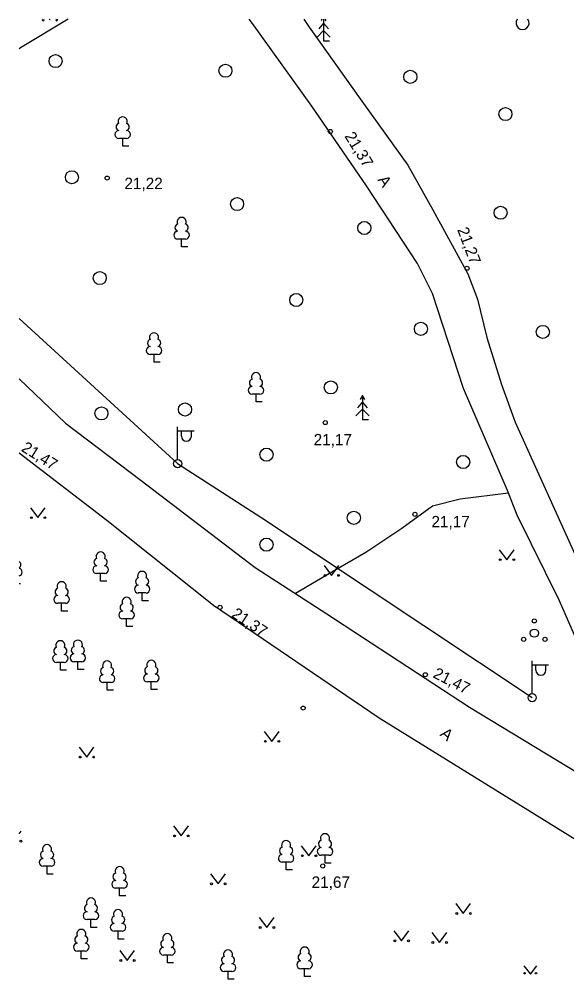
# Model space of a CAD drawing. Extents: x 714391 to 714584, y 6589993 to 6590151.
# Drawn here: x 714390.6 to 714424.1, y 6590092.2 to 6590151.1 of the extents above; entities that cross this region are included whole.
import ezdxf

# ---------------------------------------------------------------- set-up
doc = ezdxf.new("R2010")
doc.units = 0
for name, color, linetype in [('HALJASTUS', 7, 'Continuous'), ('KORGUS', 7, 'Continuous'), ('MPKAABEL', 7, 'Continuous'), ('POST', 7, 'Continuous'), ('PUU', 7, 'Continuous'), ('TEE', 7, 'Continuous')]:
    doc.layers.add(name, color=color, linetype=linetype)

msp = doc.modelspace()

# ---------------------------------------------------------------- linework, layer by layer
at = {"layer": 'HALJASTUS'}
for p, q in [((714392.483, 6590151.075), (714392.51, 6590151.04)), ((714392.51, 6590151.04), (714392.536, 6590151.075)), ((714391.327, 6590121.227), (714391.79, 6590120.62)), ((714391.79, 6590120.62), (714392.236, 6590121.227)), ((714419.987, 6590118.657), (714420.45, 6590118.05)), ((714420.45, 6590118.05), (714420.896, 6590118.657)), ((714409.277, 6590117.697), (714409.74, 6590117.09)), ((714409.74, 6590117.09), (714410.186, 6590117.697)), ((714405.627, 6590107.557), (714406.09, 6590106.95)), ((714406.09, 6590106.95), (714406.536, 6590107.557)), ((714394.307, 6590106.597), (714394.77, 6590105.99)), ((714394.77, 6590105.99), (714395.216, 6590106.597)), ((714400.077, 6590101.777), (714400.54, 6590101.17)), ((714400.54, 6590101.17), (714400.986, 6590101.777)), ((714390.649, 6590101.299), (714390.766, 6590101.457)), ((714407.887, 6590100.567), (714408.35, 6590099.96)), ((714408.35, 6590099.96), (714408.796, 6590100.567)), ((714402.337, 6590098.847), (714402.8, 6590098.24)), ((714402.8, 6590098.24), (714403.246, 6590098.847)), ((714417.327, 6590097.037), (714417.79, 6590096.43)), ((714417.79, 6590096.43), (714418.236, 6590097.037)), ((714405.317, 6590096.177), (714405.78, 6590095.57)), ((714405.78, 6590095.57), (714406.226, 6590096.177)), ((714413.547, 6590095.367), (714414.01, 6590094.76)), ((714414.01, 6590094.76), (714414.456, 6590095.367)), ((714415.867, 6590095.267), (714416.33, 6590094.66)), ((714416.33, 6590094.66), (714416.776, 6590095.267)), ((714396.787, 6590094.167), (714397.25, 6590093.56)), ((714397.25, 6590093.56), (714397.696, 6590094.167)), ((714421.484, 6590093.227), (714421.889, 6590092.722)), ((714421.889, 6590092.722), (714422.284, 6590093.227))]:
    msp.add_line(p, q, dxfattribs=at)
for points in [[(714393.647, 6590151.075), (714390.73, 6590149.32), (714390.649, 6590149.275)], [(714420.55, 6590122.12), (714417.59, 6590121.75), (714415.91, 6590121.32), (714414.04, 6590119.96), (714411.84, 6590118.48), (714409.76, 6590117.28), (714407.53, 6590115.99)]]:
    msp.add_lwpolyline(points, dxfattribs=at)
for centre, radius in [((714392.87, 6590148.52), 0.4), ((714403.25, 6590147.93), 0.4), ((714414.55, 6590147.56), 0.4), ((714420.36, 6590145.28), 0.4), ((714393.87, 6590141.42), 0.4), ((714403.96, 6590139.78), 0.4), ((714420.07, 6590139.25), 0.4), ((714411.74, 6590138.32), 0.4), ((714395.57, 6590135.26), 0.4), ((714407.58, 6590133.92), 0.4), ((714415.2, 6590132.16), 0.4), ((714422.65, 6590131.97), 0.4), ((714409.69, 6590128.58), 0.4), ((714400.78, 6590127.23), 0.4), ((714395.67, 6590126.99), 0.4), ((714405.76, 6590124.47), 0.4), ((714417.78, 6590124.02), 0.4), ((714411.1, 6590120.61), 0.4), ((714391.389, 6590120.62), 0.055), ((714392.218, 6590120.62), 0.055), ((714405.76, 6590118.97), 0.4), ((714420.049, 6590118.05), 0.055), ((714420.878, 6590118.05), 0.055), ((714409.339, 6590117.09), 0.055), ((714410.168, 6590117.09), 0.055), ((714422.13, 6590114.31), 0.125), ((714422.13, 6590113.56), 0.25), ((714421.48, 6590113.185), 0.125), ((714422.78, 6590113.185), 0.125), ((714405.689, 6590106.95), 0.055), ((714406.518, 6590106.95), 0.055), ((714394.369, 6590105.99), 0.055), ((714395.198, 6590105.99), 0.055), ((714400.139, 6590101.17), 0.055), ((714400.968, 6590101.17), 0.055), ((714390.748, 6590100.85), 0.055), ((714407.949, 6590099.96), 0.055), ((714408.778, 6590099.96), 0.055), ((714402.399, 6590098.24), 0.055), ((714403.228, 6590098.24), 0.055), ((714417.389, 6590096.43), 0.055), ((714418.218, 6590096.43), 0.055), ((714405.379, 6590095.57), 0.055), ((714406.208, 6590095.57), 0.055), ((714413.609, 6590094.76), 0.055), ((714414.438, 6590094.76), 0.055), ((714415.929, 6590094.66), 0.055), ((714416.758, 6590094.66), 0.055), ((714396.849, 6590093.56), 0.055), ((714397.678, 6590093.56), 0.055), ((714421.536, 6590092.778), 0.0428), ((714422.236, 6590092.778), 0.0452)]:
    msp.add_circle(centre, radius, dxfattribs=at)
for centre, radius, start, end in [((714392.109, 6590151.04), 0.055, 139.81459, 40.18541), ((714392.938, 6590151.04), 0.055, 139.81459, 40.18541), ((714421.41, 6590150.85), 0.4, 145.68563, 34.31437)]:
    msp.add_arc(centre, radius, start, end, dxfattribs=at)
at = {"layer": 'KORGUS'}
for centre in [(714409.66, 6590144.22), (714396.02, 6590141.37), (714418.02, 6590135.86), (714409.35, 6590126.43), (714414.83, 6590120.82), (714402.92, 6590115.14), (714415.47, 6590111.02), (714408, 6590108.98), (714409.2, 6590099.33)]:
    msp.add_circle(centre, 0.125, dxfattribs=at)
at = {"layer": 'MPKAABEL'}
for points in [[(714390.649, 6590132.781), (714400.33, 6590123.92)], [(714400.33, 6590123.92), (714405.47, 6590120.61), (714422, 6590109.62)]]:
    msp.add_lwpolyline(points, dxfattribs=at)
at = {"layer": 'POST'}
for p, q in [((714400.33, 6590124.17), (714400.33, 6590126.17)), ((714400.33, 6590125.92), (714401.33, 6590125.92)), ((714400.557, 6590125.599), (714400.557, 6590125.92)), ((714401.169, 6590125.599), (714401.169, 6590125.92)), ((714422, 6590109.87), (714422, 6590111.87)), ((714422, 6590111.62), (714423, 6590111.62)), ((714422.227, 6590111.299), (714422.227, 6590111.62)), ((714422.839, 6590111.299), (714422.839, 6590111.62))]:
    msp.add_line(p, q, dxfattribs=at)
for centre in [(714400.33, 6590123.92), (714422, 6590109.62)]:
    msp.add_circle(centre, 0.25, dxfattribs=at)
for centre in [(714400.863, 6590125.599), (714422.533, 6590111.299)]:
    msp.add_arc(centre, 0.306, 180, 0, dxfattribs=at)
at = {"layer": 'PUU'}
for p, q in [((714409.151, 6590151.075), (714409.1, 6590150.99)), ((714409.25, 6590151.075), (714409.25, 6590149.74)), ((714409.4, 6590150.99), (714409.349, 6590151.075)), ((714409.25, 6590150.84), (714408.95, 6590150.49)), ((714409.55, 6590150.49), (714409.25, 6590150.84)), ((714409.25, 6590150.39), (714408.85, 6590149.99)), ((714409.65, 6590149.99), (714409.25, 6590150.39)), ((714409.61, 6590149.74), (714409.25, 6590149.74)), ((714397.21, 6590143.795), (714396.73, 6590143.795)), ((714396.97, 6590143.32), (714396.97, 6590143.795)), ((714397.35, 6590143.32), (714396.97, 6590143.32)), ((714400.81, 6590137.645), (714400.33, 6590137.645)), ((714400.57, 6590137.17), (714400.57, 6590137.645)), ((714400.95, 6590137.17), (714400.57, 6590137.17)), ((714399.13, 6590130.595), (714398.65, 6590130.595)), ((714398.89, 6590130.12), (714398.89, 6590130.595)), ((714399.27, 6590130.12), (714398.89, 6590130.12)), ((714405.36, 6590128.165), (714404.88, 6590128.165)), ((714405.12, 6590127.69), (714405.12, 6590128.165)), ((714411.63, 6590128.09), (714411.48, 6590127.84)), ((714411.78, 6590127.84), (714411.63, 6590128.09)), ((714411.63, 6590128.09), (714411.63, 6590126.59)), ((714405.5, 6590127.69), (714405.12, 6590127.69)), ((714411.63, 6590127.69), (714411.33, 6590127.34)), ((714411.93, 6590127.34), (714411.63, 6590127.69)), ((714411.63, 6590127.24), (714411.23, 6590126.84)), ((714412.03, 6590126.84), (714411.63, 6590127.24)), ((714411.99, 6590126.59), (714411.63, 6590126.59)), ((714395.86, 6590117.205), (714395.38, 6590117.205)), ((714395.62, 6590116.73), (714395.62, 6590117.205)), ((714390.73, 6590116.58), (714390.649, 6590116.58)), ((714396, 6590116.73), (714395.62, 6590116.73)), ((714398.4, 6590116.015), (714397.92, 6590116.015)), ((714398.16, 6590115.54), (714398.16, 6590116.015)), ((714393.48, 6590115.385), (714393, 6590115.385)), ((714393.24, 6590114.91), (714393.24, 6590115.385)), ((714398.54, 6590115.54), (714398.16, 6590115.54)), ((714393.62, 6590114.91), (714393.24, 6590114.91)), ((714397.45, 6590114.435), (714396.97, 6590114.435)), ((714397.21, 6590113.96), (714397.21, 6590114.435)), ((714397.59, 6590113.96), (714397.21, 6590113.96)), ((714393.4, 6590111.775), (714392.92, 6590111.775)), ((714393.16, 6590111.3), (714393.16, 6590111.775)), ((714394.47, 6590111.815), (714393.99, 6590111.815)), ((714394.23, 6590111.34), (714394.23, 6590111.815)), ((714393.54, 6590111.3), (714393.16, 6590111.3)), ((714394.61, 6590111.34), (714394.23, 6590111.34)), ((714396.26, 6590110.545), (714395.78, 6590110.545)), ((714396.02, 6590110.07), (714396.02, 6590110.545)), ((714398.96, 6590110.585), (714398.48, 6590110.585)), ((714398.72, 6590110.11), (714398.72, 6590110.585)), ((714396.4, 6590110.07), (714396.02, 6590110.07)), ((714399.1, 6590110.11), (714398.72, 6590110.11)), ((714409.58, 6590099.985), (714409.1, 6590099.985)), ((714409.34, 6590099.51), (714409.34, 6590099.985)), ((714392.59, 6590099.315), (714392.11, 6590099.315)), ((714392.35, 6590098.84), (714392.35, 6590099.315)), ((714407.2, 6590099.565), (714406.72, 6590099.565)), ((714406.96, 6590099.09), (714406.96, 6590099.565)), ((714409.72, 6590099.51), (714409.34, 6590099.51)), ((714392.73, 6590098.84), (714392.35, 6590098.84)), ((714407.34, 6590099.09), (714406.96, 6590099.09)), ((714397.02, 6590097.975), (714396.54, 6590097.975)), ((714396.78, 6590097.5), (714396.78, 6590097.975)), ((714397.16, 6590097.5), (714396.78, 6590097.5)), ((714395.27, 6590096.055), (714394.79, 6590096.055)), ((714395.03, 6590095.58), (714395.03, 6590096.055)), ((714395.41, 6590095.58), (714395.03, 6590095.58)), ((714396.93, 6590095.345), (714396.45, 6590095.345)), ((714396.69, 6590094.87), (714396.69, 6590095.345)), ((714397.07, 6590094.87), (714396.69, 6590094.87)), ((714394.68, 6590094.135), (714394.2, 6590094.135)), ((714394.44, 6590093.66), (714394.44, 6590094.135)), ((714394.82, 6590093.66), (714394.44, 6590093.66)), ((714399.94, 6590093.885), (714399.46, 6590093.885)), ((714399.7, 6590093.41), (714399.7, 6590093.885)), ((714400.08, 6590093.41), (714399.7, 6590093.41)), ((714403.65, 6590092.885), (714403.17, 6590092.885)), ((714403.41, 6590092.41), (714403.41, 6590092.885)), ((714408.33, 6590093.055), (714407.85, 6590093.055)), ((714408.09, 6590092.58), (714408.09, 6590093.055)), ((714403.79, 6590092.41), (714403.41, 6590092.41)), ((714408.47, 6590092.58), (714408.09, 6590092.58))]:
    msp.add_line(p, q, dxfattribs=at)
for centre, radius, start, end in [((714396.8, 6590144.493), 0.233, 109.02174, 253.14154), ((714396.97, 6590144.84), 0.277, 332.5799, 207.4201), ((714397.14, 6590144.493), 0.233, 286.85082, 70.98591), ((714396.733, 6590144.032), 0.238, 90.0016, 269.3953), ((714397.207, 6590144.032), 0.238, 270.6047, 89.9984), ((714400.57, 6590138.69), 0.277, 332.5799, 207.4201), ((714400.333, 6590137.882), 0.238, 90.0016, 269.3953), ((714400.4, 6590138.343), 0.233, 109.02174, 253.14154), ((714400.74, 6590138.343), 0.233, 286.85082, 70.98591), ((714400.807, 6590137.882), 0.238, 270.6047, 89.9984), ((714398.89, 6590131.64), 0.277, 332.5799, 207.4201), ((714398.653, 6590130.832), 0.238, 90.0016, 269.3953), ((714398.72, 6590131.293), 0.233, 109.02174, 253.14154), ((714399.06, 6590131.293), 0.233, 286.85082, 70.98591), ((714399.127, 6590130.832), 0.238, 270.6047, 89.9984), ((714405.12, 6590129.21), 0.277, 332.5799, 207.4201), ((714404.883, 6590128.402), 0.238, 90.0016, 269.3953), ((714404.95, 6590128.863), 0.233, 109.02174, 253.14154), ((714405.29, 6590128.863), 0.233, 286.85082, 70.98591), ((714405.357, 6590128.402), 0.238, 270.6047, 89.9984), ((714395.45, 6590117.903), 0.233, 109.02174, 253.14154), ((714395.62, 6590118.25), 0.277, 332.5799, 207.4201), ((714395.79, 6590117.903), 0.233, 286.85082, 70.98591), ((714390.52, 6590117.753), 0.233, 303.78356, 56.21644), ((714390.587, 6590117.292), 0.238, 285.10949, 74.89051), ((714395.383, 6590117.442), 0.238, 90.0016, 269.3953), ((714395.857, 6590117.442), 0.238, 270.6047, 89.9984), ((714397.99, 6590116.713), 0.233, 109.02174, 253.14154), ((714398.16, 6590117.06), 0.277, 332.5799, 207.4201), ((714398.33, 6590116.713), 0.233, 286.85082, 70.98591), ((714393.07, 6590116.083), 0.233, 109.02174, 253.14154), ((714393.24, 6590116.43), 0.277, 332.5799, 207.4201), ((714393.41, 6590116.083), 0.233, 286.85082, 70.98591), ((714397.923, 6590116.252), 0.238, 90.0016, 269.3953), ((714398.397, 6590116.252), 0.238, 270.6047, 89.9984), ((714393.003, 6590115.622), 0.238, 90.0016, 269.3953), ((714393.477, 6590115.622), 0.238, 270.6047, 89.9984), ((714397.21, 6590115.48), 0.277, 332.5799, 207.4201), ((714397.04, 6590115.133), 0.233, 109.02174, 253.14154), ((714397.38, 6590115.133), 0.233, 286.85082, 70.98591), ((714396.973, 6590114.672), 0.238, 90.0016, 269.3953), ((714397.447, 6590114.672), 0.238, 270.6047, 89.9984), ((714393.16, 6590112.82), 0.277, 332.5799, 207.4201), ((714394.23, 6590112.86), 0.277, 332.5799, 207.4201), ((714392.923, 6590112.012), 0.238, 90.0016, 269.3953), ((714392.99, 6590112.473), 0.233, 109.02174, 253.14154), ((714393.33, 6590112.473), 0.233, 286.85082, 70.98591), ((714393.397, 6590112.012), 0.238, 270.6047, 89.9984), ((714393.993, 6590112.052), 0.238, 90.0016, 269.3953), ((714394.06, 6590112.513), 0.233, 109.02174, 253.14154), ((714394.4, 6590112.513), 0.233, 286.85082, 70.98591), ((714394.467, 6590112.052), 0.238, 270.6047, 89.9984), ((714396.02, 6590111.59), 0.277, 332.5799, 207.4201), ((714398.72, 6590111.63), 0.277, 332.5799, 207.4201), ((714395.783, 6590110.782), 0.238, 90.0016, 269.3953), ((714395.85, 6590111.243), 0.233, 109.02174, 253.14154), ((714396.19, 6590111.243), 0.233, 286.85082, 70.98591), ((714396.257, 6590110.782), 0.238, 270.6047, 89.9984), ((714398.483, 6590110.822), 0.238, 90.0016, 269.3953), ((714398.55, 6590111.283), 0.233, 109.02174, 253.14154), ((714398.89, 6590111.283), 0.233, 286.85082, 70.98591), ((714398.957, 6590110.822), 0.238, 270.6047, 89.9984), ((714409.34, 6590101.03), 0.277, 332.5799, 207.4201), ((714392.35, 6590100.36), 0.277, 332.5799, 207.4201), ((714406.79, 6590100.263), 0.233, 109.02174, 253.14154), ((714406.96, 6590100.61), 0.277, 332.5799, 207.4201), ((714407.13, 6590100.263), 0.233, 286.85082, 70.98591), ((714409.103, 6590100.222), 0.238, 90.0016, 269.3953), ((714409.17, 6590100.683), 0.233, 109.02174, 253.14154), ((714409.51, 6590100.683), 0.233, 286.85082, 70.98591), ((714409.577, 6590100.222), 0.238, 270.6047, 89.9984), ((714392.113, 6590099.552), 0.238, 90.0016, 269.3953), ((714392.18, 6590100.013), 0.233, 109.02174, 253.14154), ((714392.52, 6590100.013), 0.233, 286.85082, 70.98591), ((714392.587, 6590099.552), 0.238, 270.6047, 89.9984), ((714406.723, 6590099.802), 0.238, 90.0016, 269.3953), ((714407.197, 6590099.802), 0.238, 270.6047, 89.9984), ((714396.78, 6590099.02), 0.277, 332.5799, 207.4201), ((714396.61, 6590098.673), 0.233, 109.02174, 253.14154), ((714396.95, 6590098.673), 0.233, 286.85082, 70.98591), ((714396.543, 6590098.212), 0.238, 90.0016, 269.3953), ((714397.017, 6590098.212), 0.238, 270.6047, 89.9984), ((714394.86, 6590096.753), 0.233, 109.02174, 253.14154), ((714395.03, 6590097.1), 0.277, 332.5799, 207.4201), ((714395.2, 6590096.753), 0.233, 286.85082, 70.98591), ((714394.793, 6590096.292), 0.238, 90.0016, 269.3953), ((714395.267, 6590096.292), 0.238, 270.6047, 89.9984), ((714396.52, 6590096.043), 0.233, 109.02174, 253.14154), ((714396.69, 6590096.39), 0.277, 332.5799, 207.4201), ((714396.86, 6590096.043), 0.233, 286.85082, 70.98591), ((714396.453, 6590095.582), 0.238, 90.0016, 269.3953), ((714396.927, 6590095.582), 0.238, 270.6047, 89.9984), ((714394.44, 6590095.18), 0.277, 332.5799, 207.4201), ((714399.7, 6590094.93), 0.277, 332.5799, 207.4201), ((714394.203, 6590094.372), 0.238, 90.0016, 269.3953), ((714394.27, 6590094.833), 0.233, 109.02174, 253.14154), ((714394.61, 6590094.833), 0.233, 286.85082, 70.98591), ((714394.677, 6590094.372), 0.238, 270.6047, 89.9984), ((714399.53, 6590094.583), 0.233, 109.02174, 253.14154), ((714399.87, 6590094.583), 0.233, 286.85082, 70.98591), ((714399.463, 6590094.122), 0.238, 90.0016, 269.3953), ((714399.937, 6590094.122), 0.238, 270.6047, 89.9984), ((714403.41, 6590093.93), 0.277, 332.5799, 207.4201), ((714407.92, 6590093.753), 0.233, 109.02174, 253.14154), ((714408.09, 6590094.1), 0.277, 332.5799, 207.4201), ((714408.26, 6590093.753), 0.233, 286.85082, 70.98591), ((714403.173, 6590093.122), 0.238, 90.0016, 269.3953), ((714403.24, 6590093.583), 0.233, 109.02174, 253.14154), ((714403.58, 6590093.583), 0.233, 286.85082, 70.98591), ((714403.647, 6590093.122), 0.238, 270.6047, 89.9984), ((714407.853, 6590093.292), 0.238, 90.0016, 269.3953), ((714408.327, 6590093.292), 0.238, 270.6047, 89.9984)]:
    msp.add_arc(centre, radius, start, end, dxfattribs=at)
at = {"layer": 'TEE'}
for points in [[(714390.649, 6590129.095), (714393.48, 6590126.4), (714398.09, 6590122.89), (714405.06, 6590117.58), (714409.44, 6590114.75), (714418.17, 6590109.03), (714426.14, 6590104.21), (714428.12, 6590105.45), (714427.35, 6590107.1), (714423.67, 6590115.54), (714421.09, 6590120.78), (714420.48, 6590122.28), (714417.81, 6590128.52), (714415.91, 6590134.31), (714414.98, 6590136.15), (714411.88, 6590140.9), (714408.53, 6590145.77), (714404.9, 6590150.82), (714404.697, 6590151.075)], [(714408.052, 6590151.075), (714408.37, 6590150.6), (714411.69, 6590145.93), (714414.39, 6590142.16), (714415.93, 6590139.44), (714418.07, 6590135.51), (714418.66, 6590133.97), (714419.22, 6590131.63), (714420.13, 6590128.75), (714420.96, 6590126.45), (714424.8, 6590117.94), (714430.08, 6590107.48), (714432.094, 6590103.064)], [(714390.65, 6590124.59), (714396, 6590120.47), (714402.53, 6590115.27), (714412.65, 6590108.38), (714428.405, 6590098.635), (714430.062, 6590097.596), (714432.277, 6590096.218), (714432.498, 6590094.946), (714428.283, 6590085.404), (714423.452, 6590074.702), (714420.733, 6590068.851), (714418.831, 6590064.457), (714408.849, 6590042.202), (714401.401, 6590025.886)]]:
    msp.add_lwpolyline(points, dxfattribs=at)

# ---------------------------------------------------------------- texts
at = {"layer": 'KORGUS'}
for s, rotation, p in [('21,37', 301.80941, (714410.506, 6590143.934)), ('21,27', 290.70142, (714417.407, 6590138.22)), ('21,47', 328.15092, (714390.722, 6590124.724)), ('21,37', 326.36381, (714403.566, 6590114.586)), ('21,47', 332.95947, (714415.883, 6590110.879))]:
    msp.add_text(s, height=0.7, rotation=rotation, dxfattribs=at).set_placement(p)
for s, p in [('21,22', (714397.076, 6590140.695)), ('21,17', (714408.641, 6590125.035)), ('21,17', (714415.841, 6590120.025)), ('21,67', (714408.521, 6590097.995))]:
    msp.add_text(s, height=0.7, dxfattribs=at).set_placement(p)
at = {"layer": 'TEE'}
for rotation, p in [(303.0603, (714412.529, 6590141.262)), (319.80155, (714416.325, 6590107.329))]:
    msp.add_text('A', height=0.7, rotation=rotation, dxfattribs=at).set_placement(p)

doc.saveas('drawing.dxf')
